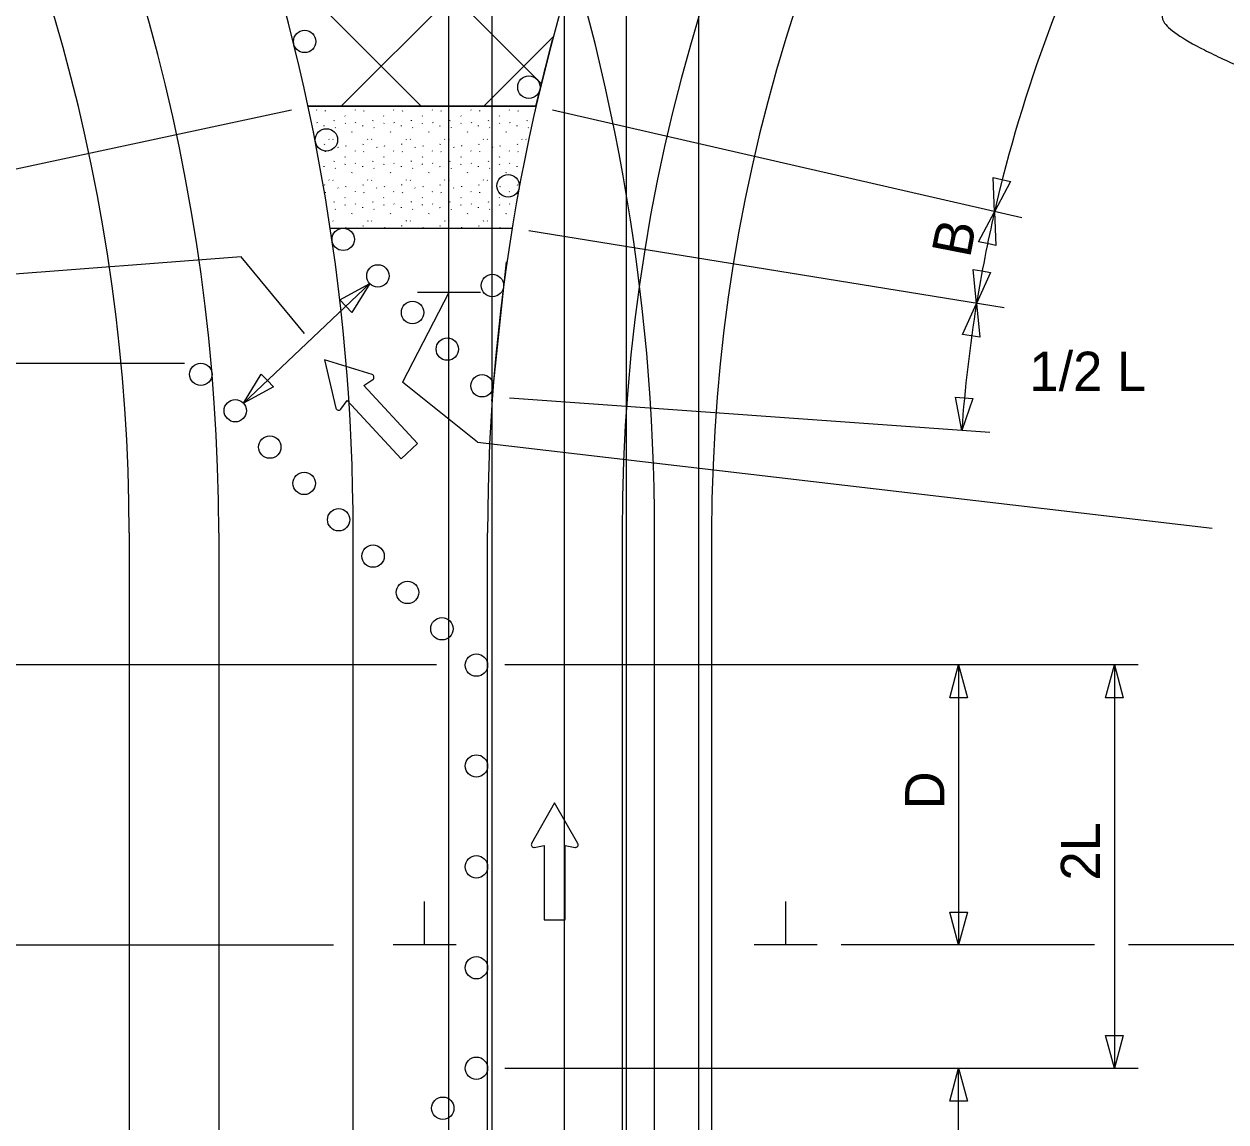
# Model space of a CAD drawing. Extents: x 16552 to 19508, y 5713 to 7079.
# Drawn here: x 16897.2 to 17111.8, y 6278.6 to 6474.6 of the extents above; entities that cross this region are included whole.
import ezdxf

# ---------------------------------------------------------------- set-up
doc = ezdxf.new("R2010")
doc.units = 0
for name, color, linetype in [('ALI_LEGAL_EX', 7, 'Continuous'), ('MT_SCRATCH_LEVEL_A', 7, 'Continuous'), ('MT_SCRATCH_LEVEL_E', 7, 'Continuous'), ('PAVT_EDGE_EX', 7, 'Continuous'), ('TRAFFIC_SIGNS_PR', 7, 'Continuous'), ('TYPICAL_TEXT_DIMEN_PR', 7, 'Continuous')]:
    doc.layers.add(name, color=color, linetype=linetype)

msp = doc.modelspace()

# ---------------------------------------------------------------- linework, layer by layer
at = {"layer": 'ALI_LEGAL_EX'}
for p, q in [((16980.68, 6974.12), (16980.68, 6155.98)), ((17004.68, 6974.12), (17004.68, 6155.98)), ((16980.68, 6877.04), (16980.68, 6013.12)), ((17004.68, 6877.04), (17004.68, 6013.12)), ((16973.01, 6139.03), (16973.01, 6639.38)), ((16993.65, 6024.8), (16993.65, 6525.15)), ((17017.65, 6024.8), (17017.65, 6525.15)), ((16955.93, 6107.09), (16955.93, 6383.76)), ((16979.93, 6107.09), (16979.93, 6383.76)), ((17009.75, 5773.57), (17009.75, 6383.76))]:
    msp.add_line(p, q, dxfattribs=at)
for points in [[(16980.7, 6407.3), (16983.32, 6432.16)], [(16955.93, 6307.09), (16955.93, 6332.09)], [(16979.93, 6307.09), (16979.93, 6332.09)]]:
    msp.add_lwpolyline(points, dxfattribs=at)
for centre, radius, start, end in [((16591.93, 6383.76), 364, 0, 40.1909), ((16645.75, 6383.76), 364, 0, 40.1909), ((17319.93, 6383.76), 340, 137.516, 180)]:
    msp.add_arc(centre, radius, start, end, dxfattribs=at)
at = {"layer": 'MT_SCRATCH_LEVEL_A'}
for p, q in [((16953.81, 6459.9), (17004.45, 6510.55)), ((16968.1, 6459.9), (16940.97, 6487.03)), ((16989.56, 6463.9), (16969.88, 6483.58)), ((16979.27, 6459.9), (16991.66, 6472.3)), ((16991.51, 6471.74), (16988.57, 6459.9)), ((16947.88, 6459.9), (16988.57, 6459.9)), ((16947.88, 6459.9), (16988.57, 6459.9)), ((16988.57, 6459.9), (16947.88, 6459.9)), ((16949.38, 6459.26), (16949.43, 6459.18)), ((16950.91, 6459.12), (16950.96, 6459.04)), ((16953.22, 6459.9), (16953.25, 6459.86)), ((16956.26, 6459.26), (16956.31, 6459.18)), ((16957.79, 6459.12), (16957.85, 6459.04)), ((16960.1, 6459.9), (16960.14, 6459.86)), ((16963.15, 6459.26), (16963.2, 6459.18)), ((16964.68, 6459.12), (16964.73, 6459.04)), ((16966.99, 6459.9), (16967.02, 6459.86)), ((16970.04, 6459.26), (16970.09, 6459.18)), ((16971.57, 6459.12), (16971.62, 6459.04)), ((16973.88, 6459.9), (16973.91, 6459.86)), ((16976.93, 6459.26), (16976.98, 6459.18)), ((16978.46, 6459.12), (16978.51, 6459.04)), ((16980.77, 6459.9), (16980.8, 6459.86)), ((16983.81, 6459.26), (16983.87, 6459.18)), ((16985.34, 6459.12), (16985.4, 6459.04)), ((16987.65, 6459.9), (16987.69, 6459.86)), ((16949.42, 6457.05), (16949.48, 6456.97)), ((16952.55, 6457.33), (16952.6, 6457.44)), ((16954.47, 6458.2), (16954.53, 6458.12)), ((16954.52, 6456.8), (16954.57, 6456.91)), ((16956.31, 6457.05), (16956.36, 6456.97)), ((16959.44, 6457.33), (16959.49, 6457.44)), ((16961.36, 6458.2), (16961.41, 6458.12)), ((16961.4, 6456.8), (16961.46, 6456.91)), ((16963.2, 6457.05), (16963.25, 6456.97)), ((16966.32, 6457.33), (16966.37, 6457.44)), ((16968.25, 6458.2), (16968.3, 6458.12)), ((16968.29, 6456.8), (16968.34, 6456.91)), ((16970.09, 6457.05), (16970.14, 6456.97)), ((16973.21, 6457.33), (16973.26, 6457.44)), ((16975.14, 6458.2), (16975.19, 6458.12)), ((16975.18, 6456.8), (16975.23, 6456.91)), ((16976.97, 6457.05), (16977.03, 6456.97)), ((16980.1, 6457.33), (16980.15, 6457.44)), ((16982.02, 6458.2), (16982.08, 6458.12)), ((16982.07, 6456.8), (16982.12, 6456.91)), ((16983.86, 6457.05), (16983.91, 6456.97)), ((16986.99, 6457.33), (16987.04, 6457.44)), ((16948.81, 6455.3), (16948.86, 6455.41)), ((16950.71, 6456.47), (16950.72, 6456.36)), ((16952.74, 6456.13), (16952.79, 6456.05)), ((16955.69, 6455.3), (16955.75, 6455.41)), ((16957.59, 6456.47), (16957.61, 6456.36)), ((16959.62, 6456.13), (16959.67, 6456.05)), ((16962.58, 6455.3), (16962.63, 6455.41)), ((16964.48, 6456.47), (16964.49, 6456.36)), ((16966.51, 6456.13), (16966.56, 6456.05)), ((16969.47, 6455.3), (16969.52, 6455.41)), ((16971.37, 6456.47), (16971.38, 6456.36)), ((16973.4, 6456.13), (16973.45, 6456.05)), ((16976.36, 6455.3), (16976.41, 6455.41)), ((16978.26, 6456.47), (16978.27, 6456.36)), ((16980.29, 6456.13), (16980.34, 6456.05)), ((16983.24, 6455.3), (16983.3, 6455.41)), ((16985.14, 6456.47), (16985.16, 6456.36)), ((16987.17, 6456.13), (16987.22, 6456.05)), ((16950.83, 6453.1), (16950.88, 6453.22)), ((16951.59, 6454.06), (16951.64, 6453.98)), ((16952.33, 6454.03), (16952.38, 6453.95)), ((16953.2, 6452.65), (16953.25, 6452.57)), ((16954.65, 6452.8), (16954.7, 6452.92)), ((16957.71, 6453.1), (16957.76, 6453.22)), ((16958.48, 6454.06), (16958.53, 6453.98)), ((16959.22, 6454.03), (16959.27, 6453.95)), ((16960.08, 6452.65), (16960.14, 6452.57)), ((16961.53, 6452.8), (16961.58, 6452.92)), ((16964.6, 6453.1), (16964.65, 6453.22)), ((16965.37, 6454.06), (16965.42, 6453.98)), ((16966.1, 6454.03), (16966.15, 6453.95)), ((16966.97, 6452.65), (16967.02, 6452.57)), ((16968.42, 6452.8), (16968.47, 6452.92)), ((16971.49, 6453.1), (16971.54, 6453.22)), ((16972.25, 6454.06), (16972.3, 6453.98)), ((16972.99, 6454.03), (16973.04, 6453.95)), ((16973.86, 6452.65), (16973.91, 6452.57)), ((16975.31, 6452.8), (16975.36, 6452.92)), ((16978.38, 6453.1), (16978.43, 6453.22)), ((16979.14, 6454.06), (16979.19, 6453.98)), ((16979.88, 6454.03), (16979.93, 6453.95)), ((16980.75, 6452.65), (16980.8, 6452.57)), ((16982.19, 6452.8), (16982.25, 6452.92)), ((16985.26, 6453.1), (16985.31, 6453.22)), ((16986.03, 6454.06), (16986.08, 6453.98)), ((16986.76, 6454.03), (16986.82, 6453.95)), ((16950.91, 6451.83), (16950.96, 6451.76)), ((16954.47, 6450.91), (16954.53, 6450.84)), ((16956.26, 6451.97), (16956.31, 6451.9)), ((16957.79, 6451.83), (16957.85, 6451.76)), ((16961.36, 6450.91), (16961.41, 6450.84)), ((16963.15, 6451.97), (16963.2, 6451.9)), ((16964.68, 6451.83), (16964.73, 6451.76)), ((16968.25, 6450.91), (16968.3, 6450.84)), ((16970.04, 6451.97), (16970.09, 6451.9)), ((16971.57, 6451.83), (16971.62, 6451.76)), ((16975.14, 6450.91), (16975.19, 6450.84)), ((16976.93, 6451.97), (16976.98, 6451.9)), ((16978.46, 6451.83), (16978.51, 6451.76)), ((16982.02, 6450.91), (16982.08, 6450.84)), ((16983.81, 6451.97), (16983.87, 6451.9)), ((16985.34, 6451.83), (16985.4, 6451.76)), ((16950.71, 6449.19), (16950.72, 6449.07)), ((16952.55, 6450.04), (16952.6, 6450.16)), ((16952.74, 6448.85), (16952.79, 6448.77)), ((16954.52, 6449.51), (16954.57, 6449.63)), ((16956.31, 6449.76), (16956.36, 6449.69)), ((16957.59, 6449.19), (16957.61, 6449.07)), ((16959.44, 6450.04), (16959.49, 6450.16)), ((16959.62, 6448.85), (16959.67, 6448.77)), ((16961.4, 6449.51), (16961.46, 6449.63)), ((16963.2, 6449.76), (16963.25, 6449.69)), ((16964.48, 6449.19), (16964.49, 6449.07)), ((16966.32, 6450.04), (16966.37, 6450.16)), ((16966.51, 6448.85), (16966.56, 6448.77)), ((16968.29, 6449.51), (16968.34, 6449.63)), ((16970.09, 6449.76), (16970.14, 6449.69)), ((16971.37, 6449.19), (16971.38, 6449.07)), ((16973.21, 6450.04), (16973.26, 6450.16)), ((16973.4, 6448.85), (16973.45, 6448.77)), ((16975.18, 6449.51), (16975.23, 6449.63)), ((16976.97, 6449.76), (16977.03, 6449.69)), ((16978.26, 6449.19), (16978.27, 6449.07)), ((16980.1, 6450.04), (16980.15, 6450.16)), ((16980.29, 6448.85), (16980.34, 6448.77)), ((16982.07, 6449.51), (16982.12, 6449.63)), ((16983.86, 6449.76), (16983.91, 6449.69)), ((16985.14, 6449.19), (16985.16, 6449.07)), ((16951.59, 6446.78), (16951.64, 6446.7)), ((16952.33, 6446.74), (16952.38, 6446.67)), ((16955.69, 6448.01), (16955.75, 6448.13)), ((16958.48, 6446.78), (16958.53, 6446.7)), ((16959.22, 6446.74), (16959.27, 6446.67)), ((16962.58, 6448.01), (16962.63, 6448.13)), ((16965.37, 6446.78), (16965.42, 6446.7)), ((16966.1, 6446.74), (16966.15, 6446.67)), ((16969.47, 6448.01), (16969.52, 6448.13)), ((16972.25, 6446.78), (16972.3, 6446.7)), ((16972.99, 6446.74), (16973.04, 6446.67)), ((16976.36, 6448.01), (16976.41, 6448.13)), ((16979.14, 6446.78), (16979.19, 6446.7)), ((16979.88, 6446.74), (16979.93, 6446.67)), ((16983.24, 6448.01), (16983.3, 6448.13)), ((16950.83, 6445.82), (16950.88, 6445.93)), ((16950.91, 6444.55), (16950.96, 6444.47)), ((16953.2, 6445.37), (16953.25, 6445.29)), ((16954.65, 6445.52), (16954.7, 6445.63)), ((16956.26, 6444.69), (16956.31, 6444.61)), ((16957.71, 6445.82), (16957.76, 6445.93)), ((16957.79, 6444.55), (16957.85, 6444.47)), ((16960.08, 6445.37), (16960.14, 6445.29)), ((16961.53, 6445.52), (16961.58, 6445.63)), ((16963.15, 6444.69), (16963.2, 6444.61)), ((16964.6, 6445.82), (16964.65, 6445.93)), ((16964.68, 6444.55), (16964.73, 6444.47)), ((16966.97, 6445.37), (16967.02, 6445.29)), ((16968.42, 6445.52), (16968.47, 6445.63)), ((16970.04, 6444.69), (16970.09, 6444.61)), ((16971.49, 6445.82), (16971.54, 6445.93)), ((16971.57, 6444.55), (16971.62, 6444.47)), ((16973.86, 6445.37), (16973.91, 6445.29)), ((16975.31, 6445.52), (16975.36, 6445.63)), ((16976.93, 6444.69), (16976.98, 6444.61)), ((16978.38, 6445.82), (16978.43, 6445.93)), ((16978.46, 6444.55), (16978.51, 6444.47)), ((16980.75, 6445.37), (16980.8, 6445.29)), ((16982.19, 6445.52), (16982.25, 6445.63)), ((16983.81, 6444.69), (16983.87, 6444.61)), ((16985.26, 6445.82), (16985.31, 6445.93)), ((16985.34, 6444.55), (16985.4, 6444.47)), ((16952.55, 6442.76), (16952.6, 6442.88)), ((16954.47, 6443.63), (16954.53, 6443.55)), ((16954.52, 6442.23), (16954.57, 6442.35)), ((16956.31, 6442.48), (16956.36, 6442.4)), ((16957.59, 6441.9), (16957.61, 6441.79)), ((16959.44, 6442.76), (16959.49, 6442.88)), ((16961.36, 6443.63), (16961.41, 6443.55)), ((16961.4, 6442.23), (16961.46, 6442.35)), ((16963.2, 6442.48), (16963.25, 6442.4)), ((16964.48, 6441.9), (16964.49, 6441.79)), ((16966.32, 6442.76), (16966.37, 6442.88)), ((16968.25, 6443.63), (16968.3, 6443.55)), ((16968.29, 6442.23), (16968.34, 6442.35)), ((16970.09, 6442.48), (16970.14, 6442.4)), ((16971.37, 6441.9), (16971.38, 6441.79)), ((16973.21, 6442.76), (16973.26, 6442.88)), ((16975.14, 6443.63), (16975.19, 6443.55)), ((16975.18, 6442.23), (16975.23, 6442.35)), ((16976.97, 6442.48), (16977.03, 6442.4)), ((16978.26, 6441.9), (16978.27, 6441.79)), ((16980.1, 6442.76), (16980.15, 6442.88)), ((16982.02, 6443.63), (16982.08, 6443.55)), ((16982.07, 6442.23), (16982.12, 6442.35)), ((16983.86, 6442.48), (16983.91, 6442.4)), ((16952.74, 6441.56), (16952.79, 6441.48)), ((16955.69, 6440.73), (16955.75, 6440.84)), ((16959.62, 6441.56), (16959.67, 6441.48)), ((16962.58, 6440.73), (16962.63, 6440.84)), ((16966.51, 6441.56), (16966.56, 6441.48)), ((16969.47, 6440.73), (16969.52, 6440.84)), ((16973.4, 6441.56), (16973.45, 6441.48)), ((16976.36, 6440.73), (16976.41, 6440.84)), ((16980.29, 6441.56), (16980.34, 6441.48)), ((16983.24, 6440.73), (16983.3, 6440.84)), ((16951.64, 6439.41), (16951.64, 6439.41)), ((16951.84, 6438.16), (16984.31, 6438.16)), ((16951.84, 6438.16), (16984.31, 6438.16)), ((16952.33, 6439.46), (16952.38, 6439.38)), ((16954.65, 6438.23), (16954.7, 6438.35)), ((16957.71, 6438.53), (16957.76, 6438.65)), ((16958.48, 6439.49), (16958.53, 6439.41)), ((16959.22, 6439.46), (16959.27, 6439.38)), ((16961.53, 6438.23), (16961.58, 6438.35)), ((16964.6, 6438.53), (16964.65, 6438.65)), ((16965.37, 6439.49), (16965.42, 6439.41)), ((16966.1, 6439.46), (16966.15, 6439.38)), ((16968.42, 6438.23), (16968.47, 6438.35)), ((16971.49, 6438.53), (16971.54, 6438.65)), ((16972.25, 6439.49), (16972.3, 6439.41)), ((16972.99, 6439.46), (16973.04, 6439.38)), ((16975.31, 6438.23), (16975.36, 6438.35)), ((16978.38, 6438.53), (16978.43, 6438.65)), ((16979.14, 6439.49), (16979.19, 6439.41)), ((16979.88, 6439.46), (16979.93, 6439.38)), ((16982.19, 6438.23), (16982.25, 6438.35))]:
    msp.add_line(p, q, dxfattribs=at)
msp.add_lwpolyline([(16947.88, 6459.9), (16988.57, 6459.9), (16991.51, 6471.74)], dxfattribs=at)
at = {"layer": 'MT_SCRATCH_LEVEL_E'}
for p, q in [((16991.9, 6335.57), (16987.79, 6328.32)), ((16996.05, 6328.32), (16991.9, 6335.57)), ((16988.27, 6327.64), (16990.05, 6327.96)), ((16990.05, 6327.96), (16990.05, 6314.7)), ((16993.79, 6314.7), (16993.79, 6327.96)), ((16993.79, 6327.96), (16995.57, 6327.64)), ((16990.05, 6314.7), (16993.79, 6314.7))]:
    msp.add_line(p, q, dxfattribs=at)
for centre, start, end in [((16988.2, 6328.1), 150.4248, 279.9638), ((16995.64, 6328.1), 260.0362, 29.7731)]:
    msp.add_arc(centre, 0.463, start, end, dxfattribs=at)
at = {"layer": 'PAVT_EDGE_EX'}
for p, q in [((16915.93, 6383.76), (16915.93, 6107.09)), ((16931.93, 6383.76), (16931.93, 6107.09)), ((17003.93, 6383.76), (17003.93, 6107.09)), ((17019.93, 6383.76), (17019.93, 6107.09))]:
    msp.add_line(p, q, dxfattribs=at)
for centre, radius, start, end in [((17319.93, 6383.76), 316, 107.923, 180), ((16591.93, 6383.76), 340, 0, 61.4862), ((17319.93, 6383.76), 300, 107.923, 180), ((16591.93, 6383.76), 324, 0, 61.4862), ((17319.93, 6383.76), 300, 180, 180.00000277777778)]:
    msp.add_arc(centre, radius, start, end, dxfattribs=at)
at = {"layer": 'TRAFFIC_SIGNS_PR'}
for centre in [(16947.27, 6471.47), (16987.31, 6463.31), (16951.15, 6453.9), (16983.59, 6445.7), (16954.16, 6436.15), (16954.16, 6436.15), (16954.16, 6436.15), (16960.35, 6429.62), (16980.79, 6427.92), (16966.54, 6423.09), (16972.74, 6416.56), (16928.74, 6412.06), (16978.94, 6410.02), (16934.89, 6405.57), (16941.04, 6399.08), (16947.19, 6392.6), (16953.34, 6386.11), (16959.48, 6379.62), (16965.63, 6373.14), (16971.78, 6366.65), (16977.93, 6360.16), (16977.93, 6360.16), (16977.93, 6342.16), (16977.93, 6324.16), (16977.93, 6306.16), (16977.93, 6288.21), (16971.93, 6281.07)]:
    msp.add_circle(centre, 2, dxfattribs=at)
at = {"layer": 'TYPICAL_TEXT_DIMEN_PR'}
for p, q in [((16860.85, 6441.29), (16944.94, 6459.28)), ((17075.31, 6439.97), (16991.54, 6459.22)), ((17070.43, 6441.09), (17070.22, 6447.16)), ((17070.22, 6447.16), (17071.75, 6446.81)), ((17073.28, 6446.45), (17070.43, 6441.09)), ((17071.75, 6446.81), (17073.28, 6446.45)), ((17067.59, 6435.73), (17070.43, 6441.09)), ((17070.43, 6441.09), (17070.65, 6435.03)), ((17072.17, 6423.92), (16987.32, 6437.68)), ((17069.12, 6435.38), (17067.59, 6435.73)), ((17070.65, 6435.03), (17069.12, 6435.38)), ((16973.04, 6426.65), (16973.04, 6434.44)), ((16935.91, 6433.02), (16850.71, 6426.47)), ((16947.27, 6419.32), (16935.91, 6433.02)), ((17067.23, 6424.72), (17066.62, 6430.76)), ((17066.62, 6430.76), (17068.17, 6430.51)), ((17067.23, 6424.72), (17066.62, 6430.76)), ((17066.62, 6430.76), (17068.17, 6430.51)), ((17069.72, 6430.26), (17067.23, 6424.72)), ((17069.72, 6430.26), (17067.23, 6424.72)), ((17068.17, 6430.51), (17069.72, 6430.26)), ((17068.17, 6430.51), (17069.72, 6430.26)), ((16958.9, 6428.25), (16936.35, 6406.94)), ((16953.56, 6425.36), (16958.9, 6428.25)), ((16958.9, 6428.25), (16955.72, 6423.08)), ((16954.64, 6424.22), (16953.56, 6425.36)), ((16973.04, 6426.65), (16964.73, 6410.68)), ((16978.66, 6426.65), (16967.41, 6426.65)), ((17064.74, 6419.19), (17067.23, 6424.72)), ((17067.23, 6424.72), (17067.84, 6418.69)), ((16955.72, 6423.08), (16954.64, 6424.22)), ((17066.29, 6418.94), (17064.74, 6419.19)), ((17067.84, 6418.69), (17066.29, 6418.94)), ((16865.26, 6414.06), (16925.83, 6414.06)), ((16959.32, 6412), (16950.83, 6414.66)), ((16950.83, 6414.66), (16952.85, 6406.02)), ((16936.35, 6406.94), (16939.53, 6412.11)), ((16939.53, 6412.11), (16940.61, 6410.97)), ((16941.69, 6409.83), (16936.35, 6406.94)), ((16940.61, 6410.97), (16941.69, 6409.83)), ((16957.82, 6410.08), (16959.44, 6411.12)), ((16967.43, 6399.7), (16957.82, 6410.08)), ((16978.14, 6399.98), (16964.73, 6410.68)), ((16953.73, 6405.83), (16954.89, 6407.37)), ((16954.89, 6407.37), (16964.5, 6396.99)), ((17069.57, 6401.67), (16983.84, 6407.81)), ((17064.58, 6402.03), (17063.44, 6407.99)), ((17063.44, 6407.99), (17065, 6407.88)), ((17066.57, 6407.76), (17064.58, 6402.03)), ((17065, 6407.88), (17066.57, 6407.76)), ((16964.5, 6396.99), (16967.43, 6399.7)), ((16978.14, 6399.98), (17109.28, 6384.63)), ((16970.82, 6360.21), (16866.93, 6360.21)), ((17096.07, 6360.21), (16982.98, 6360.21)), ((17062.46, 6354.35), (17064.03, 6360.21)), ((17064.03, 6360.21), (17065.6, 6354.35)), ((17064.03, 6360.21), (17064.03, 6310.21)), ((17090.26, 6354.35), (17091.83, 6360.21)), ((17091.83, 6360.21), (17091.83, 6288.21)), ((17091.83, 6360.21), (17093.4, 6354.35)), ((17064.03, 6354.35), (17062.46, 6354.35)), ((17065.6, 6354.35), (17064.03, 6354.35)), ((17091.83, 6354.35), (17090.26, 6354.35)), ((17093.4, 6354.35), (17091.83, 6354.35)), ((16968.68, 6310.21), (16968.68, 6318)), ((17033.15, 6310.21), (17033.15, 6318)), ((17064.03, 6310.21), (17062.46, 6316.07)), ((17062.46, 6316.07), (17064.03, 6316.07)), ((17064.03, 6316.07), (17065.6, 6316.07)), ((17065.6, 6316.07), (17064.03, 6310.21)), ((16867.03, 6310.21), (16952.43, 6310.21)), ((16974.31, 6310.21), (16963.06, 6310.21)), ((17038.78, 6310.21), (17027.53, 6310.21)), ((17088.3, 6310.21), (17043.03, 6310.21)), ((17133.57, 6310.21), (17094.37, 6310.21)), ((17091.83, 6288.21), (17090.26, 6294.07)), ((17090.26, 6294.07), (17091.83, 6294.07)), ((17091.83, 6294.07), (17093.4, 6294.07)), ((17093.4, 6294.07), (17091.83, 6288.21)), ((16982.98, 6288.21), (17096.07, 6288.21)), ((17062.46, 6282.35), (17064.03, 6288.21)), ((17064.03, 6259.65), (17064.03, 6288.21)), ((17064.03, 6288.21), (17065.6, 6282.35)), ((17064.03, 6282.35), (17062.46, 6282.35)), ((17065.6, 6282.35), (17064.03, 6282.35))]:
    msp.add_line(p, q, dxfattribs=at)
for centre, radius, start, end in [((17319.93, 6383.76), 256, 137.0843, 167.0592), ((17319.93, 6383.76), 256, 167.0592, 170.7929), ((17319.93, 6383.76), 256, 170.7929, 175.9084), ((16959.16, 6411.53), 0.494, 302.8238, 72.5607), ((16953.34, 6406.14), 0.494, 193.2124, 322.7514)]:
    msp.add_arc(centre, radius, start, end, dxfattribs=at)
msp.add_open_spline([(17095.73, 6492.44), (17127.37, 6480.93), (17124.25, 6472.36), (17101.95, 6480.48), (17098.84, 6471.91), (17137.06, 6458)], degree=2, dxfattribs=at)

# ---------------------------------------------------------------- texts
for s, rotation, p in [('B', 78.9226, (17066.04, 6432.68)), ('D', 90, (17061.47, 6334.43)), ('2L', 90, (17089.28, 6321.72))]:
    msp.add_text(s, height=7, rotation=rotation, dxfattribs=at).set_placement(p)
msp.add_text('1/2 L', height=7, dxfattribs=at).set_placement((17076.67, 6409.1))

doc.saveas('drawing.dxf')
